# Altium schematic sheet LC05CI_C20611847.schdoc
size 127 x 101 mm
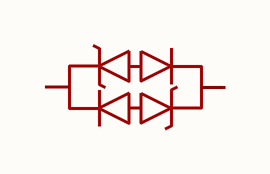
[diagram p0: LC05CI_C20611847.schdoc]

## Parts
D?  lc05ci_c20611847  [SOD-323_L1.8-W1.3-LS2.5-BI]  (value not drawn)

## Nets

Not connected (* = marked no-connect by the designer): D? 1 2

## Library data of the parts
D? = lc05ci_c20611847: Manufacturer: TECH PUBLIC(台舟); ManufacturerPart: LC05CI; AddInBom: yes; ModelId: f9eb3c564310447fa7e5a2d35bef3787; ModelTransform: 98.425,51.181,0,0,0,0,0,0,0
